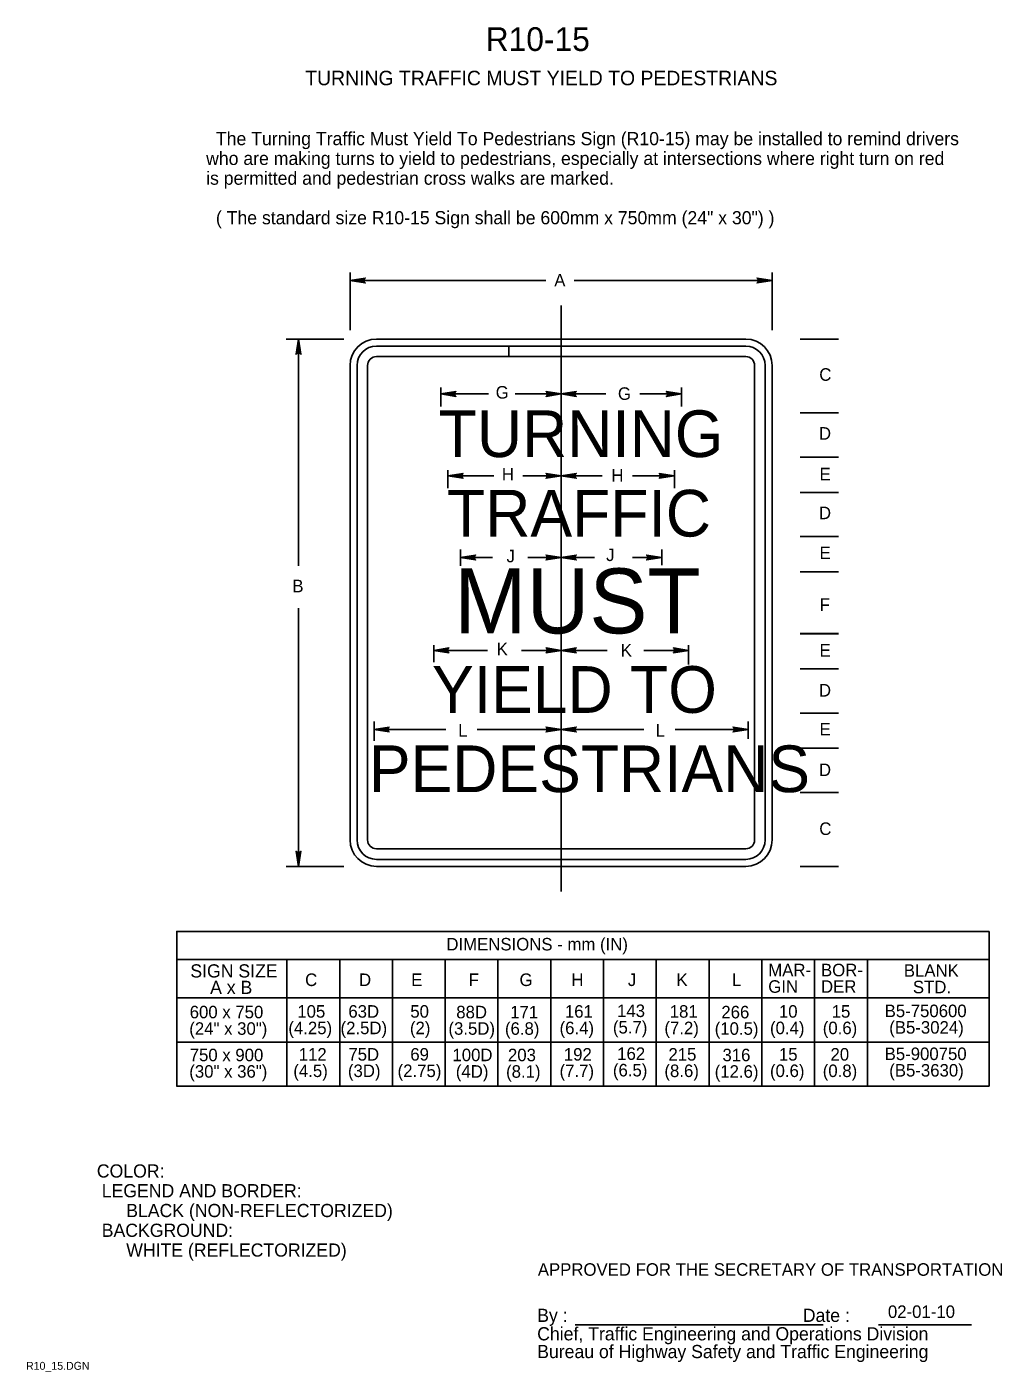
# Model space of a CAD drawing. Extents: x 0.012 to 0.196, y 0.008 to 0.263.
import ezdxf

# ---------------------------------------------------------------- set-up
doc = ezdxf.new("R2010")
doc.units = 0
for name, color, linetype in [('1', 7, 'Continuous'), ('2', 7, 'Continuous'), ('3', 7, 'Continuous'), ('4', 7, 'Continuous')]:
    doc.layers.add(name, color=color, linetype=linetype)

msp = doc.modelspace()

# ---------------------------------------------------------------- linework, layer by layer
at = {"layer": '1'}
for p, q in [((0.07278, 0.21674), (0.07278, 0.20577)), ((0.15278, 0.21674), (0.15278, 0.20577)), ((0.11278, 0.21048), (0.11278, 0.09936)), ((0.06065, 0.20411), (0.07162, 0.20411)), ((0.06301, 0.20411), (0.06301, 0.16109)), ((0.14778, 0.20411), (0.07778, 0.20411)), ((0.07778, 0.20278), (0.10287, 0.20278)), ((0.10287, 0.20078), (0.10287, 0.20278)), ((0.10287, 0.20278), (0.14778, 0.20278)), ((0.10287, 0.20278), (0.10287, 0.20078)), ((0.07278, 0.19911), (0.07278, 0.10911)), ((0.07411, 0.10911), (0.07411, 0.19911)), ((0.07611, 0.19911), (0.07611, 0.10911)), ((0.10287, 0.20078), (0.07778, 0.20078)), ((0.14778, 0.20078), (0.10287, 0.20078)), ((0.14945, 0.10911), (0.14945, 0.19911)), ((0.15145, 0.19911), (0.15145, 0.10911)), ((0.15278, 0.10911), (0.15278, 0.19911)), ((0.08998, 0.19492), (0.08998, 0.19133)), ((0.11278, 0.19599), (0.11278, 0.19133)), ((0.13558, 0.19492), (0.13558, 0.19133)), ((0.09132, 0.17927), (0.09132, 0.17581)), ((0.11278, 0.17927), (0.11278, 0.17581)), ((0.13424, 0.17927), (0.13424, 0.17581)), ((0.09371, 0.16423), (0.09371, 0.16112)), ((0.11278, 0.16423), (0.11278, 0.16124)), ((0.13185, 0.16423), (0.13185, 0.16124)), ((0.06301, 0.15305), (0.06301, 0.10411)), ((0.08865, 0.14608), (0.08865, 0.14286)), ((0.11278, 0.14608), (0.11278, 0.14286)), ((0.13691, 0.14608), (0.13691, 0.14238)), ((0.07732, 0.1316), (0.07732, 0.12793)), ((0.11278, 0.1316), (0.11278, 0.12793)), ((0.14824, 0.1316), (0.14824, 0.12829)), ((0.07778, 0.10744), (0.14778, 0.10744)), ((0.14778, 0.10544), (0.07778, 0.10544)), ((0.06065, 0.10411), (0.07162, 0.10411)), ((0.07778, 0.10411), (0.14778, 0.10411)), ((0.11544, 0.01717), (0.16242, 0.01717)), ((0.17295, 0.01717), (0.19056, 0.01717))]:
    msp.add_line(p, q, dxfattribs=at)
for points in [[(0.07551, 0.21487), (0.0754, 0.21507), (0.07278, 0.21521), (0.07551, 0.21487), (0.07565, 0.21475), (0.07278, 0.21521), (0.0754, 0.21534), (0.0755, 0.21554), (0.07278, 0.21521), (0.07565, 0.21567), (0.0755, 0.21554)], [(0.15006, 0.21555), (0.15016, 0.21536), (0.15278, 0.21521), (0.15006, 0.21555), (0.14992, 0.21567), (0.15278, 0.21521), (0.15016, 0.21508), (0.15006, 0.21489), (0.15278, 0.21521), (0.14992, 0.21476), (0.15006, 0.21489)], [(0.06267, 0.20138), (0.06287, 0.20148), (0.06301, 0.20411), (0.06267, 0.20138), (0.06255, 0.20124), (0.06301, 0.20411), (0.06314, 0.20149), (0.06333, 0.20139), (0.06301, 0.20411), (0.06346, 0.20124), (0.06333, 0.20139)], [(0.09271, 0.19336), (0.0926, 0.19355), (0.08998, 0.1937), (0.09271, 0.19336), (0.09285, 0.19324), (0.08998, 0.1937), (0.0926, 0.19383), (0.0927, 0.19402), (0.08998, 0.1937), (0.09285, 0.19415), (0.0927, 0.19402)], [(0.11006, 0.19404), (0.11016, 0.19384), (0.11278, 0.1937), (0.11006, 0.19404), (0.10992, 0.19416), (0.11278, 0.1937), (0.11016, 0.19357), (0.11006, 0.19337), (0.11278, 0.1937), (0.10992, 0.19324), (0.11006, 0.19337)], [(0.11551, 0.19336), (0.1154, 0.19355), (0.11278, 0.1937), (0.11551, 0.19336), (0.11565, 0.19324), (0.11278, 0.1937), (0.1154, 0.19383), (0.1155, 0.19402), (0.11278, 0.1937), (0.11565, 0.19415), (0.1155, 0.19402)], [(0.13286, 0.19404), (0.13296, 0.19384), (0.13558, 0.1937), (0.13286, 0.19404), (0.13272, 0.19416), (0.13558, 0.1937), (0.13296, 0.19357), (0.13286, 0.19337), (0.13558, 0.1937), (0.13272, 0.19324), (0.13286, 0.19337)], [(0.09405, 0.17783), (0.09394, 0.17803), (0.09132, 0.17818), (0.09405, 0.17783), (0.09419, 0.17771), (0.09132, 0.17818), (0.09394, 0.17831), (0.09404, 0.1785), (0.09132, 0.17818), (0.09419, 0.17863), (0.09404, 0.1785)], [(0.11006, 0.17852), (0.11016, 0.17832), (0.11278, 0.17818), (0.11006, 0.17852), (0.10992, 0.17864), (0.11278, 0.17818), (0.11016, 0.17805), (0.11006, 0.17785), (0.11278, 0.17818), (0.10992, 0.17772), (0.11006, 0.17785)], [(0.11551, 0.17783), (0.1154, 0.17803), (0.11278, 0.17818), (0.11551, 0.17783), (0.11565, 0.17771), (0.11278, 0.17818), (0.1154, 0.17831), (0.1155, 0.1785), (0.11278, 0.17818), (0.11565, 0.17863), (0.1155, 0.1785)], [(0.13152, 0.17852), (0.13162, 0.17832), (0.13424, 0.17818), (0.13152, 0.17852), (0.13138, 0.17864), (0.13424, 0.17818), (0.13162, 0.17805), (0.13152, 0.17785), (0.13424, 0.17818), (0.13138, 0.17772), (0.13152, 0.17785)], [(0.09644, 0.16235), (0.09633, 0.16255), (0.09371, 0.16269), (0.09644, 0.16235), (0.09658, 0.16223), (0.09371, 0.16269), (0.09633, 0.16282), (0.09643, 0.16302), (0.09371, 0.16269), (0.09658, 0.16315), (0.09643, 0.16302)], [(0.11006, 0.16303), (0.11016, 0.16284), (0.11278, 0.16269), (0.11006, 0.16303), (0.10992, 0.16315), (0.11278, 0.16269), (0.11016, 0.16256), (0.11006, 0.16237), (0.11278, 0.16269), (0.10992, 0.16224), (0.11006, 0.16237)], [(0.11551, 0.16235), (0.1154, 0.16255), (0.11278, 0.16269), (0.11551, 0.16235), (0.11565, 0.16223), (0.11278, 0.16269), (0.1154, 0.16282), (0.1155, 0.16302), (0.11278, 0.16269), (0.11565, 0.16315), (0.1155, 0.16302)], [(0.12913, 0.16303), (0.12923, 0.16284), (0.13185, 0.16269), (0.12913, 0.16303), (0.12899, 0.16315), (0.13185, 0.16269), (0.12923, 0.16256), (0.12913, 0.16237), (0.13185, 0.16269), (0.12899, 0.16224), (0.12913, 0.16237)], [(0.09138, 0.14473), (0.09127, 0.14493), (0.08865, 0.14507), (0.09138, 0.14473), (0.09152, 0.14461), (0.08865, 0.14507), (0.09127, 0.1452), (0.09137, 0.1454), (0.08865, 0.14507), (0.09152, 0.14553), (0.09137, 0.1454)], [(0.11006, 0.14541), (0.11016, 0.14522), (0.11278, 0.14507), (0.11006, 0.14541), (0.10992, 0.14553), (0.11278, 0.14507), (0.11016, 0.14494), (0.11006, 0.14475), (0.11278, 0.14507), (0.10992, 0.14462), (0.11006, 0.14475)], [(0.11551, 0.14473), (0.1154, 0.14493), (0.11278, 0.14507), (0.11551, 0.14473), (0.11565, 0.14461), (0.11278, 0.14507), (0.1154, 0.1452), (0.1155, 0.1454), (0.11278, 0.14507), (0.11565, 0.14553), (0.1155, 0.1454)], [(0.13419, 0.14541), (0.13429, 0.14522), (0.13691, 0.14507), (0.13419, 0.14541), (0.13405, 0.14553), (0.13691, 0.14507), (0.13429, 0.14494), (0.13419, 0.14475), (0.13691, 0.14507), (0.13405, 0.14462), (0.13419, 0.14475)], [(0.08005, 0.12973), (0.07994, 0.12993), (0.07732, 0.13007), (0.08005, 0.12973), (0.08019, 0.12961), (0.07732, 0.13007), (0.07994, 0.1302), (0.08004, 0.1304), (0.07732, 0.13007), (0.08019, 0.13053), (0.08004, 0.1304)], [(0.11006, 0.13041), (0.11016, 0.13022), (0.11278, 0.13007), (0.11006, 0.13041), (0.10992, 0.13053), (0.11278, 0.13007), (0.11016, 0.12994), (0.11006, 0.12975), (0.11278, 0.13007), (0.10992, 0.12962), (0.11006, 0.12975)], [(0.11551, 0.12973), (0.1154, 0.12993), (0.11278, 0.13007), (0.11551, 0.12973), (0.11565, 0.12961), (0.11278, 0.13007), (0.1154, 0.1302), (0.1155, 0.1304), (0.11278, 0.13007), (0.11565, 0.13053), (0.1155, 0.1304)], [(0.14552, 0.13041), (0.14562, 0.13022), (0.14824, 0.13007), (0.14552, 0.13041), (0.14538, 0.13053), (0.14824, 0.13007), (0.14562, 0.12994), (0.14552, 0.12975), (0.14824, 0.13007), (0.14538, 0.12962), (0.14552, 0.12975)], [(0.06335, 0.10683), (0.06315, 0.10673), (0.06301, 0.10411), (0.06335, 0.10683), (0.06347, 0.10697), (0.06301, 0.10411), (0.06288, 0.10673), (0.06269, 0.10682), (0.06301, 0.10411), (0.06255, 0.10697), (0.06269, 0.10682)]]:
    msp.add_lwpolyline(points, dxfattribs=at)
for centre, radius, start, end in [((0.07778, 0.19911), 0.005, 90, 180), ((0.14778, 0.19911), 0.005, 0, 90), ((0.07778, 0.19911), 0.00367, 90, 180), ((0.14778, 0.19911), 0.00367, 0, 90), ((0.07778, 0.19911), 0.00167, 90, 180), ((0.14778, 0.19911), 0.00167, 0, 90), ((0.07778, 0.10911), 0.005, 180, 270), ((0.07778, 0.10911), 0.00367, 180, 270), ((0.07778, 0.10911), 0.00167, 180, 270), ((0.14778, 0.10911), 0.005, 270, 0), ((0.14778, 0.10911), 0.00167, 270, 0), ((0.14778, 0.10911), 0.00367, 270, 0)]:
    msp.add_arc(centre, radius, start, end, dxfattribs=at)
at = {"layer": '3'}
for p, q in [((0.07278, 0.21521), (0.10989, 0.21521)), ((0.11528, 0.21521), (0.15278, 0.21521)), ((0.15811, 0.20411), (0.16534, 0.20411)), ((0.08998, 0.1937), (0.09905, 0.1937)), ((0.10407, 0.1937), (0.11278, 0.1937)), ((0.11278, 0.1937), (0.12126, 0.1937)), ((0.12771, 0.1937), (0.13558, 0.1937)), ((0.15811, 0.19011), (0.16534, 0.19011)), ((0.15811, 0.18171), (0.16534, 0.18171)), ((0.09132, 0.17818), (0.10001, 0.17818)), ((0.1055, 0.17818), (0.11278, 0.17818)), ((0.11278, 0.17818), (0.12055, 0.17818)), ((0.12628, 0.17818), (0.13424, 0.17818)), ((0.15811, 0.17504), (0.16534, 0.17504)), ((0.15811, 0.16664), (0.16534, 0.16664)), ((0.09371, 0.16269), (0.09977, 0.16269)), ((0.10646, 0.16269), (0.11278, 0.16269)), ((0.11911, 0.16269), (0.11278, 0.16269)), ((0.13185, 0.16269), (0.12628, 0.16269)), ((0.15811, 0.15997), (0.16534, 0.15997)), ((0.15811, 0.14825), (0.16534, 0.14825)), ((0.15811, 0.14824), (0.16534, 0.14824)), ((0.08865, 0.14507), (0.09881, 0.14507)), ((0.10526, 0.14507), (0.11278, 0.14507)), ((0.11278, 0.14507), (0.1215, 0.14507)), ((0.12843, 0.14507), (0.13691, 0.14507)), ((0.15811, 0.14158), (0.16534, 0.14158)), ((0.15811, 0.13318), (0.16534, 0.13318)), ((0.07732, 0.13007), (0.09093, 0.13007)), ((0.0969, 0.13007), (0.11278, 0.13007)), ((0.12843, 0.13007), (0.11278, 0.13007)), ((0.14824, 0.13007), (0.1344, 0.13007)), ((0.15811, 0.12651), (0.16534, 0.12651)), ((0.15811, 0.11811), (0.16534, 0.11811)), ((0.15811, 0.10411), (0.16534, 0.10411)), ((0.03989, 0.09178), (0.19389, 0.09178)), ((0.03993, 0.09179), (0.03993, 0.06241)), ((0.19389, 0.09178), (0.19389, 0.06241)), ((0.19389, 0.08644), (0.03993, 0.08644)), ((0.06082, 0.0864), (0.06082, 0.06241)), ((0.07082, 0.0864), (0.07082, 0.06241)), ((0.08082, 0.0864), (0.08082, 0.06241)), ((0.09082, 0.0864), (0.09082, 0.06241)), ((0.10082, 0.0864), (0.10082, 0.06241)), ((0.11082, 0.0864), (0.11082, 0.06241)), ((0.12082, 0.0864), (0.12082, 0.06241)), ((0.13082, 0.0864), (0.13082, 0.06241)), ((0.14082, 0.0864), (0.14082, 0.06241)), ((0.15082, 0.0864), (0.15082, 0.06241)), ((0.16082, 0.0864), (0.16082, 0.06241)), ((0.16082, 0.0864), (0.16082, 0.06241)), ((0.17082, 0.0864), (0.17082, 0.06241)), ((0.03989, 0.07916), (0.19389, 0.07916)), ((0.03989, 0.07078), (0.19389, 0.07078)), ((0.03989, 0.06241), (0.19389, 0.06241))]:
    msp.add_line(p, q, dxfattribs=at)

# ---------------------------------------------------------------- texts
at = {"layer": '1'}
for s, height, p in [('R10-15', 0.0045, (0.09849, 0.25875)), ('TURNING TRAFFIC MUST YIELD TO PEDESTRIANS', 0.0027503, (0.06428, 0.25225)), ('MUST', 0.012322, (0.09252, 0.14829)), ('YIELD TO', 0.008859, (0.08832, 0.13322)), ('PEDESTRIANS', 0.0088591, (0.07635, 0.11818)), ('COLOR:', 0.0025, (0.02479, 0.04509)), (' LEGEND AND BORDER:', 0.0024998, (0.02479, 0.04134)), ('      BLACK (NON-REFLECTORIZED)', 0.0024998, (0.02479, 0.03759)), (' BACKGROUND:', 0.0024998, (0.02479, 0.03384)), ('      WHITE (REFLECTORIZED)', 0.0024998, (0.02479, 0.03009)), ('APPROVED FOR THE SECRETARY OF TRANSPORTATION', 0.0023752, (0.10837, 0.02646)), ('By :                                                Date :', 0.0024998, (0.10825, 0.01771)), ('Chief, Traffic Engineering and Operations Division', 0.0024998, (0.10825, 0.01421)), ('Bureau of Highway Safety and Traffic Engineering', 0.0024998, (0.10825, 0.01084)), ('R10_15.DGN', 0.0015, (0.01137, 0.00863))]:
    msp.add_text(s, height=height, dxfattribs=at).set_placement(p)
for s, p in [('TURNING', (0.08959, 0.18173)), ('TRAFFIC', (0.09117, 0.16666))]:
    msp.add_text(s, height=0.008859, rotation=360, dxfattribs=at).set_placement(p)
at = {"layer": '2'}
for s, p in [('  The Turning Traffic Must Yield To Pedestrians Sign (R10-15) may be installed to remind drivers', (0.0455, 0.24088)), ('who are making turns to yield to pedestrians, especially at intersections where right turn on red', (0.0455, 0.23713)), ('is permitted and pedestrian cross walks are marked.', (0.0455, 0.23338)), ('  ( The standard size R10-15 Sign shall be 600mm x 750mm (24" x 30") )', (0.0455, 0.22588))]:
    msp.add_text(s, height=0.0024998, dxfattribs=at).set_placement(p)
at = {"layer": '3'}
for s, height, p in [('A', 0.00238, (0.11148, 0.21409)), ('C', 0.00238, (0.16171, 0.1962)), ('G', 0.00238, (0.10038, 0.19282)), ('G', 0.00238, (0.12355, 0.19258)), ('D', 0.00238, (0.16164, 0.18503)), ('H', 0.00238, (0.10154, 0.1773)), ('H', 0.00238, (0.12231, 0.17706)), ('E', 0.00238, (0.16176, 0.17732)), ('D', 0.00238, (0.16164, 0.16995)), ('J', 0.00238, (0.10244, 0.16177)), ('J', 0.00238, (0.12131, 0.16201)), ('E', 0.00238, (0.16176, 0.16237)), ('B', 0.00238, (0.06184, 0.15609)), ('F', 0.00238, (0.1618, 0.15255)), ('K', 0.00238, (0.10055, 0.14414)), ('E', 0.00238, (0.16176, 0.14389)), ('D', 0.00238, (0.16164, 0.13631)), ('L', 0.00238, (0.09328, 0.1287)), ('E', 0.00238, (0.16176, 0.12894)), ('D', 0.00238, (0.16164, 0.12123)), ('C', 0.00238, (0.16171, 0.11006)), ('D', 0.00238, (0.07448, 0.08141)), ('E', 0.00238, (0.08437, 0.08141)), ('F', 0.00238, (0.09525, 0.08141)), ('G', 0.00238, (0.1049, 0.08141)), ('H', 0.00238, (0.11472, 0.08141)), ('J', 0.00238, (0.12543, 0.08141)), ('K', 0.00238, (0.13464, 0.08141)), ('L', 0.00238, (0.14517, 0.08141)), ('105', 0.002375, (0.06278, 0.07541)), ('50', 0.002375, (0.0842, 0.07541)), ('88D', 0.002375, (0.09291, 0.07529)), ('171', 0.002375, (0.10314, 0.07528)), ('161', 0.002375, (0.1135, 0.07541)), ('143', 0.002375, (0.12339, 0.07553)), ('181', 0.002375, (0.13337, 0.07541)), ('266', 0.002375, (0.14315, 0.07528)), ('10', 0.002375, (0.15406, 0.07541)), ('15', 0.002375, (0.16406, 0.07541)), ('(4.25)', 0.002375, (0.06109, 0.07228)), ('(2)', 0.002375, (0.08413, 0.07228)), ('(3.5D)', 0.002375, (0.09143, 0.07217)), ('(6.8)', 0.002375, (0.10214, 0.07216)), ('(6.4)', 0.002375, (0.11249, 0.07228)), ('(5.7)', 0.002375, (0.1226, 0.07241)), ('(7.2)', 0.002375, (0.13236, 0.07228)), ('(10.5)', 0.002375, (0.14189, 0.07216)), ('(0.4)', 0.002375, (0.15237, 0.07228)), ('(0.6)', 0.002375, (0.16237, 0.07228)), ('112', 0.002375, (0.06305, 0.06727)), ('69', 0.002375, (0.0842, 0.06727)), ('100D', 0.002375, (0.09219, 0.06716)), ('203', 0.002375, (0.10271, 0.06715)), ('192', 0.002375, (0.1133, 0.06727)), ('162', 0.002375, (0.12341, 0.0674)), ('215', 0.002375, (0.13312, 0.06727)), ('316', 0.002375, (0.14336, 0.06715)), ('15', 0.002375, (0.15406, 0.06727)), ('20', 0.002375, (0.16384, 0.06727)), ('(4.5)', 0.002375, (0.06203, 0.06415)), ('(2.75)', 0.002375, (0.08179, 0.06415)), ('(4D)', 0.002375, (0.09283, 0.06403)), ('(8.1)', 0.002375, (0.10235, 0.06402)), ('(7.7)', 0.002375, (0.11249, 0.06415)), ('(6.5)', 0.002375, (0.1226, 0.06427)), ('(8.6)', 0.002375, (0.13236, 0.06415)), ('(12.6)', 0.002375, (0.14189, 0.06402)), ('(0.6)', 0.002375, (0.15237, 0.06415)), ('(0.8)', 0.002375, (0.16237, 0.06415))]:
    msp.add_text(s, height=height, rotation=360, dxfattribs=at).set_placement(p)
for s, height, p in [('K', 0.00238, (0.12408, 0.1439)), ('L', 0.00238, (0.13071, 0.1287)), ('DIMENSIONS - mm (IN)', 0.0023752, (0.09104, 0.08816)), ('SIGN SIZE', 0.0025, (0.04251, 0.08303)), ('MAR-', 0.002375, (0.15204, 0.08326)), ('BOR-', 0.002375, (0.16204, 0.08326)), ('BLANK', 0.002375, (0.17774, 0.08317)), ('A x B', 0.0025, (0.04626, 0.07991)), ('C', 0.00238, (0.06426, 0.08141)), ('GIN', 0.002375, (0.15204, 0.08013)), ('DER', 0.002375, (0.16204, 0.08013)), ('STD.', 0.002375, (0.17945, 0.08004)), ('600 x 750', 0.002375, (0.04239, 0.07529)), ('63D', 0.002375, (0.07246, 0.07541)), ('B5-750600', 0.002375, (0.1741, 0.07551)), ('(24" x 30")', 0.0023752, (0.04231, 0.07216)), ('(2.5D)', 0.002375, (0.07098, 0.07228)), ('(B5-3024)', 0.002375, (0.17497, 0.07238)), ('750 x 900', 0.002375, (0.04239, 0.06715)), ('75D', 0.002375, (0.07246, 0.06727)), ('B5-900750', 0.002375, (0.1741, 0.06737)), ('(30" x 36")', 0.0023752, (0.04231, 0.06403)), ('(3D)', 0.002375, (0.07238, 0.06415)), ('(B5-3630)', 0.002375, (0.17497, 0.06424))]:
    msp.add_text(s, height=height, dxfattribs=at).set_placement(p)
at = {"layer": '4'}
msp.add_text('02-01-10', height=0.002375, dxfattribs=at).set_placement((0.17472, 0.01846))

doc.saveas('drawing.dxf')
